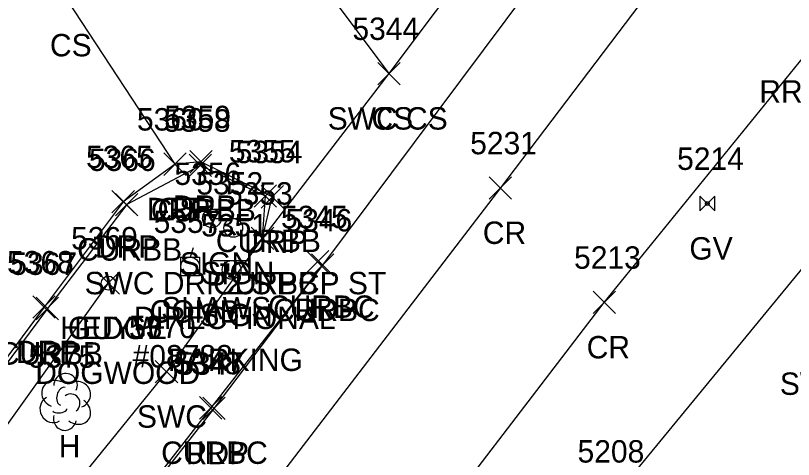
# Model space of a CAD drawing. Extents: x 1618146 to 1620418, y 640749 to 641927.
# Drawn here: x 1620219.4 to 1620288.8, y 640931.1 to 640970.7 of the extents above; entities that cross this region are included whole.
import ezdxf

# ---------------------------------------------------------------- set-up
doc = ezdxf.new("R2010")
doc.units = 0
for name, color, linetype in [('L_A', 7, 'Continuous'), ('L_C', 7, 'Continuous'), ('L_I', 7, 'Continuous'), ('L_TIC', 7, 'Continuous'), ('LAHR', 7, 'Continuous'), ('LELB', 7, 'Continuous'), ('LTD', 7, 'Continuous'), ('P_A', 7, 'Continuous'), ('P_I', 7, 'Continuous'), ('P_TIC', 7, 'Continuous'), ('PET', 7, 'Continuous'), ('PRC', 7, 'Continuous'), ('R_A', 7, 'Continuous'), ('R_I', 7, 'Continuous'), ('R_TIC', 7, 'Continuous'), ('RC', 7, 'Continuous'), ('RDP', 7, 'Continuous'), ('RSW', 7, 'Continuous'), ('S_A', 7, 'Continuous'), ('S_C', 7, 'Continuous'), ('S_I', 7, 'Continuous'), ('SSGN', 7, 'Continuous'), ('U_A', 7, 'Continuous'), ('U_C', 7, 'Continuous'), ('U_I', 7, 'Continuous'), ('UP', 7, 'Continuous'), ('UPGW', 7, 'Continuous'), ('UWV', 7, 'Continuous')]:
    doc.layers.add(name, color=color, linetype=linetype)

msp = doc.modelspace()

# ---------------------------------------------------------------- linework, layer by layer
at = {"layer": 'L_TIC'}
for points in [[(1620251.715, 640964.558), (1620253.715, 640966.558)], [(1620253.715, 640964.558), (1620251.715, 640966.558)], [(1620232.64, 640956.473), (1620234.64, 640958.473)], [(1620234.64, 640956.473), (1620232.64, 640958.473)], [(1620226.694, 640945.866), (1620228.694, 640947.866)], [(1620228.694, 640945.866), (1620226.694, 640947.866)]]:
    msp.add_lwpolyline(points, dxfattribs=at)
at = {"layer": 'LAHR'}
msp.add_lwpolyline([(1620227.694, 640946.866), (1620213.218, 640926.628), (1620203.694, 640915.312)], dxfattribs=at)
at = {"layer": 'LELB'}
for points in [[(1620197.401, 641048.219), (1620210.432, 641029.281), (1620224.447, 641006.96), (1620238.859, 640984.097), (1620252.715, 640965.558)], [(1620233.64, 640957.473), (1620224.048, 640972.091), (1620213.517, 640987.716), (1620195.916, 641017.15), (1620183.58, 641035.329)]]:
    msp.add_lwpolyline(points, dxfattribs=at)
at = {"layer": 'LTD'}
msp.add_line((1620223.84, 640936.312), (1620223.84, 640936.312), dxfattribs=at)
msp.add_line((1620223.84, 640936.312), (1620223.84, 640936.312), dxfattribs=at)
msp.add_arc((1620223.887, 640937.746), 1.047, 335.52715, 180.95627, dxfattribs=at)
for centre, major_axis, ratio, start_param, end_param in [((1620223.048, 640936.978), (1.21, -0.512), 0.895232, 1.570796, 4.712389), ((1620223.631, 640936.77), (-0.208, -0.792), 0.645439, 3.141593, 6.283185), ((1620224.881, 640936.895), (-1.141, -0.483), 0.949671, 1.570796, 4.712389), ((1620224.34, 640936.145), (-0.5, 0.667), 0.989748, 3.141593, 6.283185), ((1620222.757, 640935.603), (0.584, -1.042), 0.959034, 3.141593, 6.283185), ((1620224.84, 640935.479), (-1.09, 0.792), 0.841452, 1.570796, 4.712389), ((1620223.382, 640935.562), (-0.625, -0.083), 0.423636, 0, 3.141593), ((1620223.84, 640934.812), (0.265, 1.061), 0.942809, 1.570796, 4.712389)]:
    msp.add_ellipse(centre, major_axis=major_axis, ratio=ratio, start_param=start_param, end_param=end_param, dxfattribs=at)
at = {"layer": 'P_TIC'}
for points in [[(1620261.646, 640954.357), (1620263.646, 640956.357)], [(1620263.646, 640954.357), (1620261.646, 640956.357)], [(1620245.8, 640947.475), (1620247.8, 640949.475)], [(1620247.8, 640947.475), (1620245.8, 640949.475)], [(1620270.906, 640944.144), (1620272.906, 640946.144)], [(1620272.906, 640944.144), (1620270.906, 640946.144)], [(1620236.104, 640934.681), (1620238.104, 640936.681)], [(1620238.104, 640934.681), (1620236.104, 640936.681)]]:
    msp.add_lwpolyline(points, dxfattribs=at)
at = {"layer": 'PET'}
msp.add_lwpolyline([(1620359.618, 641102.741), (1620357.552, 641099.276), (1620341.731, 641075.022), (1620339.541, 641071.666), (1620329.909, 641058.991), (1620323.975, 641051.239), (1620317.974, 641043.478), (1620299.64, 641019.571), (1620282.799, 640996.951), (1620281.456, 640995.25), (1620278.195, 640990.782), (1620276.89, 640989.311), (1620275.826, 640987.688), (1620269.888, 640979.335), (1620267.257, 640975.908), (1620246.8, 640948.475), (1620237.104, 640935.681), (1620207.924, 640898.413)], dxfattribs=at)
at = {"layer": 'PRC'}
for points in [[(1620362.761, 641090.181), (1620340.683, 641059.759), (1620325.328, 641039.403), (1620305.343, 641012.417), (1620285.981, 640987.098), (1620282.921, 640982.142), (1620262.646, 640955.357), (1620239.617, 640925.265), (1620211.715, 640891.88)], [(1620224.798, 640884.187), (1620252.423, 640919.672), (1620271.906, 640945.144), (1620290.437, 640967.965), (1620293.935, 640972.261), (1620320.636, 641007.736), (1620341.521, 641037.703), (1620358.234, 641062.028), (1620372.9, 641083.065)], [(1620386.404, 641071.706), (1620361.021, 641035.235), (1620336.241, 641002.906), (1620316.225, 640977.168), (1620300.323, 640960.311), (1620296.609, 640956.784), (1620272.862, 640927.85), (1620252.181, 640901.579), (1620233.904, 640877.595)]]:
    msp.add_lwpolyline(points, dxfattribs=at)
at = {"layer": 'R_TIC'}
for points in [[(1620251.715, 640964.558), (1620253.715, 640966.558)], [(1620253.715, 640964.558), (1620251.715, 640966.558)], [(1620232.64, 640956.473), (1620234.64, 640958.473)], [(1620234.64, 640956.473), (1620232.64, 640958.473)], [(1620234.947, 640956.684), (1620236.947, 640958.684)], [(1620236.947, 640956.684), (1620234.947, 640958.684)], [(1620234.897, 640956.364), (1620236.897, 640958.364)], [(1620236.897, 640956.364), (1620234.897, 640958.364)], [(1620240.697, 640953.632), (1620242.697, 640955.632)], [(1620242.697, 640953.632), (1620240.697, 640955.632)], [(1620228.014, 640953.121), (1620230.014, 640955.121)], [(1620230.014, 640953.121), (1620228.014, 640955.121)], [(1620241.306, 640953.562), (1620243.306, 640955.562)], [(1620243.306, 640953.562), (1620241.306, 640955.562)], [(1620228.329, 640952.868), (1620230.329, 640954.868)], [(1620230.329, 640952.868), (1620228.329, 640954.868)], [(1620240.442, 640949.866), (1620242.442, 640951.866)], [(1620242.442, 640949.866), (1620240.442, 640951.866)], [(1620240.442, 640949.866), (1620242.442, 640951.866)], [(1620242.442, 640949.866), (1620240.442, 640951.866)], [(1620240.442, 640949.866), (1620242.442, 640951.866)], [(1620242.442, 640949.866), (1620240.442, 640951.866)], [(1620245.343, 640947.761), (1620247.343, 640949.761)], [(1620247.343, 640947.761), (1620245.343, 640949.761)], [(1620245.8, 640947.475), (1620247.8, 640949.475)], [(1620247.8, 640947.475), (1620245.8, 640949.475)], [(1620220.966, 640943.726), (1620222.966, 640945.726)], [(1620222.966, 640943.726), (1620220.966, 640945.726)], [(1620221.262, 640943.594), (1620223.262, 640945.594)], [(1620223.262, 640943.594), (1620221.262, 640945.594)], [(1620231.883, 640937.96), (1620233.883, 640939.96)], [(1620233.883, 640937.96), (1620231.883, 640939.96)], [(1620235.82, 640934.733), (1620237.82, 640936.733)], [(1620237.82, 640934.733), (1620235.82, 640936.733)]]:
    msp.add_lwpolyline(points, dxfattribs=at)
at = {"layer": 'RC'}
for points in [[(1620241.442, 640950.866), (1620241.697, 640954.632), (1620235.897, 640957.364), (1620229.329, 640953.868), (1620222.262, 640944.594), (1620207.295, 640924.468), (1620194.434, 640906.852)], [(1620246.343, 640948.761), (1620246.8, 640948.475), (1620236.82, 640935.733), (1620207.783, 640898.448)]]:
    msp.add_lwpolyline(points, dxfattribs=at)
at = {"layer": 'RDP'}
msp.add_lwpolyline([(1620241.442, 640950.866), (1620242.306, 640954.562), (1620235.947, 640957.684), (1620233.64, 640957.473), (1620229.014, 640954.121), (1620221.966, 640944.726), (1620207.113, 640924.702), (1620194.229, 640907.042)], dxfattribs=at)
at = {"layer": 'RSW'}
msp.add_lwpolyline([(1620273.827, 640994.382), (1620271.861, 640991.557), (1620269.183, 640988.021), (1620264.777, 640981.848), (1620262.749, 640979.054), (1620260.968, 640976.582), (1620252.715, 640965.558), (1620241.442, 640950.866), (1620232.883, 640938.96), (1620218.2, 640920.806), (1620210.672, 640910.804), (1620202.49, 640900.646)], dxfattribs=at)
at = {"layer": 'SSGN'}
for p, q in [((1620235.276, 640953.474), (1620238.609, 640953.474)), ((1620236.923, 640952.641), (1620236.923, 640952.641)), ((1620237.179, 640952.616), (1620240.512, 640952.616)), ((1620238.826, 640951.783), (1620238.826, 640951.783)), ((1620237.034, 640948.877), (1620240.367, 640948.877)), ((1620238.681, 640948.043), (1620238.681, 640948.043))]:
    msp.add_line(p, q, dxfattribs=at)
for centre in [(1620236.923, 640952.641), (1620238.826, 640951.783), (1620238.681, 640948.043)]:
    msp.add_circle(centre, 0.833, dxfattribs=at)
at = {"layer": 'UP'}
for p, q in [((1620235.244, 640950.006), (1620234.994, 640949.173)), ((1620234.161, 640947.506), (1620234.161, 640949.173)), ((1620234.161, 640949.173), (1620235.827, 640949.173)), ((1620235.827, 640949.173), (1620235.827, 640947.506)), ((1620234.994, 640948.339), (1620234.994, 640948.339)), ((1620235.827, 640947.506), (1620234.161, 640947.506)), ((1620234.744, 640946.673), (1620234.994, 640947.506))]:
    msp.add_line(p, q, dxfattribs=at)
msp.add_circle((1620234.994, 640948.339), 0.833, dxfattribs=at)
at = {"layer": 'UPGW'}
for radius in [0.625, 0.0833]:
    msp.add_circle((1620227.694, 640946.866), radius, dxfattribs=at)
at = {"layer": 'UWV'}
for p, q in [((1620280.426, 640954.629), (1620281.759, 640953.296)), ((1620281.759, 640954.629), (1620280.426, 640953.296))]:
    msp.add_line(p, q, dxfattribs=at)
for points in [[(1620280.426, 640954.629), (1620280.426, 640953.296)], [(1620281.759, 640953.296), (1620281.759, 640954.629)]]:
    msp.add_lwpolyline(points, dxfattribs=at)
msp.add_circle((1620281.092, 640953.962), 0.167, dxfattribs=at)

# ---------------------------------------------------------------- texts
at = {"layer": 'L_A'}
for s, p in [('CS', (1620222.489, 640967.091)), ('CS', (1620251.156, 640960.558)), ('CS', (1620232.081, 640952.473)), ('HEDGE', (1620223.395, 640941.866)), ('H', (1620223.273, 640931.312))]:
    msp.add_text(s, height=2, dxfattribs=at).set_placement(p)
at = {"layer": 'L_C'}
msp.add_text('DOGWOOD', height=2, dxfattribs=at).set_placement((1620221.182, 640937.866))
at = {"layer": 'L_I'}
for s, p in [('5344', (1620249.456, 640968.558)), ('5360', (1620230.247, 640960.473)), ('5369', (1620224.379, 640949.866)), ('5375', (1620220.58, 640939.312))]:
    msp.add_text(s, height=2, dxfattribs=at).set_placement(p)
at = {"layer": 'P_A'}
for s, p in [('CR', (1620261.079, 640950.357)), ('RDP', (1620244.288, 640943.475)), ('CR', (1620270.339, 640940.144)), ('RDP', (1620234.593, 640930.681))]:
    msp.add_text(s, height=2, dxfattribs=at).set_placement(p)
at = {"layer": 'P_I'}
for s, p in [('5231', (1620259.953, 640958.357)), ('5346', (1620243.485, 640951.475)), ('5213', (1620269.214, 640948.144)), ('5347', (1620233.845, 640938.681)), ('5208', (1620269.524, 640930.85))]:
    msp.add_text(s, height=2, dxfattribs=at).set_placement(p)
at = {"layer": 'R_A'}
for s, p in [('RRRAIL', (1620285.728, 640962.965)), ('SWC CS', (1620247.251, 640960.558)), ('DRP', (1620231.128, 640952.473)), ('CURBB', (1620231.48, 640952.364)), ('DRP', (1620233.435, 640952.684)), ('CURBB', (1620237.28, 640949.632)), ('DRP', (1620239.794, 640949.562)), ('CURBB', (1620224.912, 640948.868)), ('DRP', (1620226.503, 640949.121)), ('SWC DRP2 ST CP ST', (1620225.576, 640945.866)), ('CURBB', (1620237.025, 640945.866)), ('DRP', (1620238.931, 640945.866)), ('CURBC', (1620241.926, 640943.761)), ('CURBC', (1620242.382, 640943.475)), ('CURBB', (1620217.845, 640939.594)), ('DRP', (1620219.455, 640939.726)), ('SWC SWC2 RDP ST', (1620287.559, 640936.889)), ('SWC SWC2 RDP ST', (1620287.559, 640936.889)), ('SWC', (1620230.245, 640933.96)), ('CURBC', (1620232.403, 640930.733))]:
    msp.add_text(s, height=2, dxfattribs=at).set_placement(p)
at = {"layer": 'R_I'}
for s, p in [('5344', (1620249.456, 640968.558)), ('5359', (1620232.679, 640960.684)), ('5360', (1620230.247, 640960.473)), ('5358', (1620232.638, 640960.364)), ('5365', (1620225.707, 640957.121)), ('5355', (1620238.438, 640957.632)), ('5354', (1620239.046, 640957.562)), ('5366', (1620225.967, 640956.868)), ('5353', (1620238.183, 640953.866)), ('5353', (1620238.183, 640953.866)), ('5353', (1620238.183, 640953.866)), ('5345', (1620243.084, 640951.761)), ('5346', (1620243.485, 640951.475)), ('5368', (1620218.659, 640947.726)), ('5367', (1620218.955, 640947.594)), ('5370', (1620229.536, 640941.96)), ('5348', (1620233.561, 640938.733))]:
    msp.add_text(s, height=2, dxfattribs=at).set_placement(p)
at = {"layer": 'S_A'}
for p in [(1620234.061, 640947.621), (1620235.964, 640946.762), (1620235.819, 640943.023)]:
    msp.add_text('SIGN', height=2, dxfattribs=at).set_placement(p)
at = {"layer": 'S_C'}
for s, p in [('SHAWS', (1620232.399, 640943.621)), ('DIRECTIONAL', (1620229.972, 640942.762)), ('PARKING', (1620233, 640939.023))]:
    msp.add_text(s, height=2, dxfattribs=at).set_placement(p)
at = {"layer": 'S_I'}
for s, p in [('5356', (1620233.588, 640955.621)), ('5352', (1620235.546, 640954.762)), ('5351', (1620235.968, 640951.023))]:
    msp.add_text(s, height=2, dxfattribs=at).set_placement(p)
at = {"layer": 'U_A'}
for s, p in [('GV', (1620279.494, 640948.962)), ('COMB', (1620231.38, 640943.339)), ('GUYW', (1620224.088, 640941.866))]:
    msp.add_text(s, height=2, dxfattribs=at).set_placement(p)
at = {"layer": 'U_C'}
msp.add_text('#08788', height=2, dxfattribs=at).set_placement((1620229.86, 640939.339))
at = {"layer": 'U_I'}
for s, p in [('5214', (1620278.4, 640956.962)), ('5357', (1620231.734, 640951.339)), ('5369', (1620224.379, 640949.866))]:
    msp.add_text(s, height=2, dxfattribs=at).set_placement(p)

doc.saveas('drawing.dxf')
